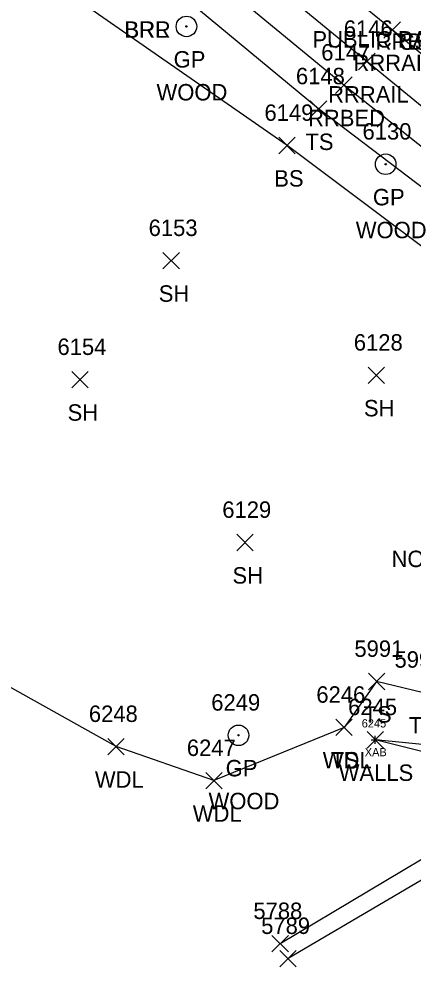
# Model space of a CAD drawing. Extents: x 1618146 to 1620418, y 640749 to 641927.
# Drawn here: x 1619881.9 to 1619929.8, y 641249.8 to 641365.2 of the extents above; entities that cross this region are included whole.
import ezdxf

# ---------------------------------------------------------------- set-up
doc = ezdxf.new("R2010")
doc.units = 0
for name, color, linetype in [('B_A', 7, 'Continuous'), ('B_I', 7, 'Continuous'), ('B_TIC', 7, 'Continuous'), ('BSUBM', 7, 'Continuous'), ('L_A', 7, 'Continuous'), ('L_I', 7, 'Continuous'), ('L_TIC', 7, 'Continuous'), ('LAWA', 7, 'Continuous'), ('LAWE', 7, 'Continuous'), ('LELB', 7, 'Continuous'), ('LWS', 7, 'Continuous'), ('R_A', 7, 'Continuous'), ('R_C', 7, 'Continuous'), ('R_I', 7, 'Continuous'), ('R_TIC', 7, 'Continuous'), ('RGP', 7, 'Continuous'), ('RR', 7, 'Continuous'), ('RRB', 7, 'Continuous'), ('S_C', 7, 'Continuous')]:
    doc.layers.add(name, color=color, linetype=linetype)

msp = doc.modelspace()

# ---------------------------------------------------------------- linework, layer by layer
at = {"layer": 'B_TIC'}
msp.add_line((1619925.25, 641277.54), (1619925.32, 641277.54), dxfattribs=at)
for points in [[(1619925.24, 641277.04), (1619925.24, 641278.04)], [(1619924.74, 641277.54), (1619925.74, 641277.54)]]:
    msp.add_lwpolyline(points, dxfattribs=at)
at = {"layer": 'BSUBM'}
msp.add_lwpolyline([(1619944.71, 641272.68), (1619925.24, 641277.54)], dxfattribs=at)
at = {"layer": 'L_TIC'}
for points in [[(1619917.33, 641353.28), (1619919.33, 641355.28)], [(1619919.33, 641353.28), (1619917.33, 641355.28)], [(1619913.51, 641348.83), (1619915.51, 641350.83)], [(1619915.51, 641348.83), (1619913.51, 641350.83)], [(1619899.41, 641334.82), (1619901.41, 641336.82)], [(1619901.41, 641334.82), (1619899.41, 641336.82)], [(1619888.32, 641320.35), (1619890.32, 641322.35)], [(1619890.32, 641320.35), (1619888.32, 641322.35)], [(1619924.37, 641320.88), (1619926.37, 641322.88)], [(1619926.37, 641320.88), (1619924.37, 641322.88)], [(1619908.38, 641300.54), (1619910.38, 641302.54)], [(1619910.38, 641300.54), (1619908.38, 641302.54)], [(1619924.4, 641283.63), (1619926.4, 641285.63)], [(1619926.4, 641283.63), (1619924.4, 641285.63)], [(1619924.4, 641283.63), (1619926.4, 641285.63)], [(1619926.4, 641283.63), (1619924.4, 641285.63)], [(1619920.44, 641278.05), (1619922.44, 641280.05)], [(1619922.44, 641278.05), (1619920.44, 641280.05)], [(1619920.44, 641278.05), (1619922.44, 641280.05)], [(1619922.44, 641278.05), (1619920.44, 641280.05)], [(1619924.24, 641276.54), (1619926.24, 641278.54)], [(1619926.24, 641276.54), (1619924.24, 641278.54)], [(1619892.71, 641275.71), (1619894.71, 641277.71)], [(1619894.71, 641275.71), (1619892.71, 641277.71)], [(1619904.62, 641271.57), (1619906.62, 641273.57)], [(1619906.62, 641271.57), (1619904.62, 641273.57)], [(1619912.67, 641251.74), (1619914.67, 641253.74)], [(1619914.67, 641251.74), (1619912.67, 641253.74)], [(1619913.63, 641249.92), (1619915.63, 641251.92)], [(1619915.63, 641249.92), (1619913.63, 641251.92)]]:
    msp.add_lwpolyline(points, dxfattribs=at)
at = {"layer": 'LAWA'}
msp.add_lwpolyline([(1619921.44, 641279.05), (1619905.62, 641272.57), (1619893.71, 641276.71), (1619869.02, 641290.53), (1619837.83, 641306.7), (1619802.84, 641333.96), (1619763.69, 641358.69), (1619736.06, 641375.92), (1619695.27, 641389.27)], dxfattribs=at)
at = {"layer": 'LAWE'}
msp.add_lwpolyline([(1620171.86, 641355.85), (1620152.34, 641338.2), (1620129.96, 641324.85), (1620111.93, 641317.84), (1620096.25, 641317.33), (1620096.2, 641316.75), (1620094.16, 641317.06), (1620094.28, 641315.29), (1620071.24, 641300.59), (1620050.39, 641293.63), (1620030.98, 641297.72), (1620009.6, 641296.43), (1619997.99, 641289.69), (1619969.13, 641278.68), (1619952.14, 641274.33), (1619935.16, 641265.54), (1619913.67, 641252.74)], dxfattribs=at)
at = {"layer": 'LELB'}
for points in [[(1619966.34, 641319.18), (1619952.77, 641322.95), (1619937.07, 641332.93), (1619914.51, 641349.83), (1619848.68, 641395.56), (1619808.65, 641436.47), (1619772.36, 641467.89)], [(1619938.91, 641338.68), (1619918.33, 641354.28), (1619884.43, 641382.4)], [(1620094.86, 641313.59), (1620072.65, 641294.84), (1620058.23, 641288.21), (1620031.72, 641288.47), (1620010.9, 641284.85), (1620001.9, 641278.17), (1619970.88, 641271.33), (1619953.58, 641271.43), (1619935.99, 641263.46), (1619914.63, 641250.92)], [(1619925.4, 641284.63), (1619921.44, 641279.05)], [(1619936.3, 641276.43), (1619930.93, 641283.31), (1619925.4, 641284.63)]]:
    msp.add_lwpolyline(points, dxfattribs=at)
at = {"layer": 'LWS'}
msp.add_lwpolyline([(1619967.69, 641296.54), (1619960.5, 641289.6), (1619958.9, 641290.69), (1619960.48, 641289.24), (1619950.67, 641280.47), (1619949.65, 641281.11), (1619950.01, 641280.09), (1619943.65, 641275.59), (1619936.3, 641276.43), (1619925.24, 641277.54)], dxfattribs=at)
at = {"layer": 'R_TIC'}
for points in [[(1619926.3, 641362.88), (1619928.3, 641364.88)], [(1619928.3, 641362.88), (1619926.3, 641364.88)], [(1619923.21, 641359.05), (1619925.21, 641361.05)], [(1619925.21, 641359.05), (1619923.21, 641361.05)], [(1619920.41, 641356.17), (1619922.41, 641358.17)], [(1619922.41, 641356.17), (1619920.41, 641358.17)]]:
    msp.add_lwpolyline(points, dxfattribs=at)
at = {"layer": 'RGP'}
for p, q in [((1619902.27, 641364.31), (1619902.27, 641364.31)), ((1619926.51, 641347.55), (1619926.51, 641347.55)), ((1619908.6, 641278.09), (1619908.6, 641278.09))]:
    msp.add_line(p, q, dxfattribs=at)
for centre, radius in [((1619902.27, 641364.31), 1.25), ((1619902.27, 641364.31), 0.0833), ((1619926.51, 641347.55), 1.25), ((1619926.51, 641347.55), 0.0833), ((1619908.6, 641278.09), 1.25), ((1619908.6, 641278.09), 0.0833)]:
    msp.add_circle(centre, radius, dxfattribs=at)
at = {"layer": 'RR'}
for points in [[(1620192.15, 641127.79), (1620168.31, 641155.99), (1620153.36, 641171.84), (1620133.44, 641191.99), (1620110.11, 641213.08), (1620101.47, 641220.64), (1620055.36, 641258.68), (1620021.94, 641286.1), (1619984.2, 641317.18), (1619946.81, 641347.8), (1619927.3, 641363.88), (1619890.89, 641393.62), (1619862.55, 641416.89)], [(1620190.75, 641121.59), (1620164.76, 641152.66), (1620149.83, 641168.39), (1620129.76, 641188.51), (1620106.88, 641209.4), (1620098.4, 641216.88), (1620053.4, 641253.96), (1620018.83, 641282.24), (1619980.56, 641313.63), (1619944.22, 641343.67), (1619924.21, 641360.05), (1619888.22, 641389.6), (1619859.16, 641413.43)]]:
    msp.add_lwpolyline(points, dxfattribs=at)
at = {"layer": 'RRB'}
msp.add_lwpolyline([(1619977.87, 641310.92), (1619966.34, 641319.18), (1619955.14, 641328.07), (1619947.13, 641336.24), (1619940.39, 641342.13), (1619921.41, 641357.17), (1619886.68, 641385.78), (1619856.81, 641410.87), (1619815.24, 641443.99), (1619779.42, 641474.24), (1619751.61, 641498.17), (1619728.14, 641518.29), (1619703.69, 641537.28), (1619683.35, 641552.45), (1619653.86, 641573.06)], dxfattribs=at)

# ---------------------------------------------------------------- texts
at = {"layer": 'B_A'}
msp.add_text('XAB', height=1, dxfattribs=at).set_placement((1619923.96, 641275.54))
at = {"layer": 'B_I'}
msp.add_text('6245', height=1, dxfattribs=at).set_placement((1619923.59, 641279.04))
at = {"layer": 'L_A'}
for s, p in [('BRR', (1619894.7, 641362.93)), ('BRL', (1619894.75, 641362.93)), ('CS', (1619928.08, 641361.47)), ('TS', (1619916.74, 641349.28)), ('BS', (1619912.95, 641344.83)), ('SH', (1619898.9, 641330.82)), ('SH', (1619887.81, 641316.35)), ('SH', (1619923.86, 641316.88)), ('SH', (1619907.87, 641296.54)), ('TS', (1619923.81, 641279.63)), ('TS', (1619923.81, 641279.63)), ('TS', (1619929.34, 641278.31)), ('WDL', (1619918.85, 641274.05)), ('TS', (1619919.84, 641274.05)), ('WALLS', (1619920.79, 641272.54)), ('WDL', (1619891.13, 641271.71)), ('WDL', (1619903.04, 641267.57))]:
    msp.add_text(s, height=2, dxfattribs=at).set_placement(p)
at = {"layer": 'L_I'}
for s, p in [('6148', (1619915.59, 641357.28)), ('6149', (1619911.76, 641352.83)), ('6153', (1619897.67, 641338.82)), ('6128', (1619922.63, 641324.88)), ('6154', (1619886.58, 641324.35)), ('6129', (1619906.63, 641304.54)), ('5991', (1619922.7, 641287.63)), ('5991', (1619922.7, 641287.63)), ('5990', (1619927.58, 641286.31)), ('6246', (1619918.07, 641282.05)), ('6246', (1619918.07, 641282.05)), ('6245', (1619921.94, 641280.54)), ('6248', (1619890.4, 641279.71)), ('6247', (1619902.32, 641275.57)), ('5788', (1619910.41, 641255.74)), ('5789', (1619911.36, 641253.92))]:
    msp.add_text(s, height=2, dxfattribs=at).set_placement(p)
at = {"layer": 'R_A'}
for s, p in [('RRBED', (1619925.28, 641361.47)), ('GP', (1619900.71, 641359.31)), ('RRRAIL', (1619922.59, 641358.88)), ('RRRAIL', (1619919.5, 641355.05)), ('RRBED', (1619917.06, 641352.17)), ('GP', (1619924.95, 641342.55)), ('GP', (1619907.04, 641273.09))]:
    msp.add_text(s, height=2, dxfattribs=at).set_placement(p)
at = {"layer": 'R_C'}
for p in [(1619898.63, 641355.31), (1619922.87, 641338.55), (1619904.96, 641269.09)]:
    msp.add_text('WOOD', height=2, dxfattribs=at).set_placement(p)
at = {"layer": 'R_I'}
for s, p in [('6146', (1619921.41, 641363.05)), ('6147', (1619918.67, 641360.17)), ('6130', (1619923.69, 641350.55)), ('6249', (1619905.29, 641281.09))]:
    msp.add_text(s, height=2, dxfattribs=at).set_placement(p)
at = {"layer": 'S_C'}
for s, p in [('PUBLIC PARKING ONLY', (1619917.59, 641361.74)), ('NO PARKING', (1619927.22, 641298.55))]:
    msp.add_text(s, height=2, dxfattribs=at).set_placement(p)

doc.saveas('drawing.dxf')
